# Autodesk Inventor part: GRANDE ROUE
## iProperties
Created: 2004-11
Part Number: GRANDE ROUE
Document SubType Name: Modeling
Designer: Bruno
Manufacturer: Standard
Standards Organization: Custom
Author: Bruno
Comments: m = 2mm Z = 100 Diamètre primitif = 200mm
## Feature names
1. Base1
2. Extrusion1
